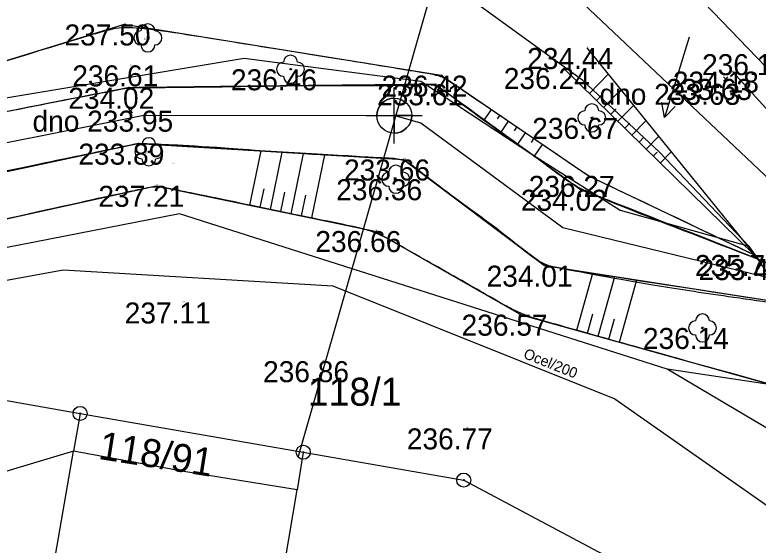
# Model space of a CAD drawing. Extents: x -555757 to -553364, y -1100723 to -1096439.
# Drawn here: x -554111.1 to -554058.1, y -1100615 to -1100577.1 of the extents above; entities that cross this region are included whole.
import ezdxf

# ---------------------------------------------------------------- set-up
doc = ezdxf.new("R2010")
doc.units = 0
for name, color, linetype in [('00_NÁVRH - 0.18 mm', 7, 'Continuous'), ('00_NÁVRH - 0.35 mm', 7, 'Continuous'), ('00_NÁVRH - Kóty výškové', 7, 'Continuous'), ('00_NÁVRH - Řezy', 7, 'Continuous'), ('01_HLADINA', 7, 'Continuous'), ('05_SÍTĚ - plynovod STL', 7, 'Continuous'), ('30', 7, 'Continuous'), ('C$SLO$PARCELY', 7, 'Continuous'), ('Geodet. výšky - netisknuté', 7, 'Continuous'), ('HRANA$SVAHU', 7, 'Continuous'), ('HRANICE$PARCELY', 7, 'Continuous'), ('OSA$KOLEJI', 7, 'Continuous'), ('POPIS', 7, 'Continuous'), ('ROZHRANI', 7, 'Continuous'), ('SLOUPY', 7, 'Continuous'), ('STROMY', 7, 'Continuous'), ('VSTUP', 7, 'Continuous'), ('VYSKA_PODR_BOD', 7, 'Continuous'), ('VYSKOVE$SRAFY', 7, 'Continuous'), ('ZNA$KY$KULTUR', 7, 'Continuous')]:
    doc.layers.add(name, color=color, linetype=linetype)

# ---------------------------------------------------------------- blocks, each defined once
blk = doc.blocks.new('POINT_DISPLAY')
blk.add_line((0, 0), (0, 0))
blk = doc.blocks.new('8$02')
at = {"layer": 'ZNA$KY$KULTUR'}
for p, q in [((0.864, 2.855), (-0.89, -2.882)), ((-0.89, -2.882), (-1.083, -1.802)), ((-0.89, -2.882), (-0.125, -2.095))]:
    blk.add_line(p, q, dxfattribs=at)
blk = doc.blocks.new('1$05')
at = {"layer": 'SLOUPY'}
for radius in [0.5, 0.032]:
    blk.add_circle((0, 0), radius, dxfattribs=at)
blk = doc.blocks.new('BOD')
at = {"layer": 'POPIS'}
for p, q in [((-0.283, -0.283), (0.283, 0.283)), ((-0.283, 0.283), (0.283, -0.283))]:
    blk.add_line(p, q, dxfattribs=at)
blk = doc.blocks.new('3$13')
at = {"layer": 'STROMY'}
blk.add_circle((0, 0), 0.05, dxfattribs=at)
for centre, start, end in [((0, 0.5), 0, 180), ((-0.5, 0), 90, 270), ((0.5, 0), 270, 90), ((0, -0.5), 180, 0)]:
    blk.add_arc(centre, 0.5, start, end, dxfattribs=at)
blk = doc.blocks.new('ZN_Výšková kóta - Půdorys')
for p, q in [((0, -2), (0, 2)), ((-2, 0), (2, 0))]:
    blk.add_line(p, q)
for points in [[(-1.25, 0), (0, 0), (0, 1.25)], [(1.25, 0), (0, 0), (0, -1.25)]]:
    blk.add_lwpolyline(points)
blk.add_circle((0, 0), 1.25)
for start, end in [(90, 180), (270, 0)]:
    blk.add_arc((0, 0), 1.25, start, end)

msp = doc.modelspace()

# ---------------------------------------------------------------- linework, layer by layer
at = {"layer": '00_NÁVRH - 0.18 mm'}
msp.add_lwpolyline([(-554047.016, -1100597.399), (-554056.765, -1100596.021), (-554072.01, -1100592.304), (-554082.146, -1100584.823), (-554084.051, -1100584.283), (-554102.031, -1100584.313), (-554134.225, -1100590.74), (-554163.98, -1100595.962)], dxfattribs=at)
for points in [[(-554058.34, -1100594.24), (-554064.27, -1100591.415), (-554069.894, -1100588.736), (-554070.2, -1100588.59), (-554070.622, -1100588.302), (-554073.49, -1100586.347), (-554075.45, -1100585.01), (-554079.1, -1100582.531), (-554080.049, -1100581.874), (-554080.7, -1100581.481), (-554081.481, -1100581.304), (-554087.875, -1100580.272), (-554092.015, -1100579.605), (-554097.661, -1100578.708), (-554101.142, -1100578.133), (-554103.33, -1100577.967), (-554104.353, -1100578.095), (-554110.104, -1100579.897), (-554119.235, -1100582.7), (-554134.394, -1100587.389), (-554135.14, -1100587.62), (-554135.88, -1100587.767), (-554163.968, -1100593.356), (-554164.64, -1100593.5), (-554165.523, -1100593.676), (-554179.48, -1100596.685), (-554194.32, -1100599.87), (-554206.989, -1100602.104), (-554211.391, -1100602.887), (-554215.452, -1100603.598), (-554218.301, -1100604.127), (-554220.59, -1100604.491), (-554221.645, -1100604.411), (-554222.588, -1100604.119), (-554224.36, -1100602.886), (-554226.55, -1100601.265), (-554230.862, -1100598.151), (-554231.32, -1100597.82), (-554232.374, -1100596.759), (-554235.586, -1100593.426), (-554239.515, -1100589.37), (-554243.986, -1100584.748), (-554247.71, -1100580.92), (-554249.936, -1100577.477), (-554252.665, -1100573.15), (-554257.62, -1100565.38), (-554264.631, -1100555.299), (-554268.645, -1100549.529), (-554269.73, -1100547.97), (-554270.489, -1100547.211), (-554275.85, -1100541.875), (-554281.97, -1100535.78), (-554287.906, -1100531.237), (-554302.937, -1100521.677), (-554058.34, -1100594.24), (-554302.937, -1100521.677)], [(-554047.86, -1100606.09), (-554063.146, -1100601.815), (-554071.814, -1100599.393), (-554074.245, -1100598.71), (-554074.95, -1100598.43), (-554075.799, -1100598.044), (-554076.704, -1100597.516), (-554082.278, -1100594.33), (-554084.54, -1100593.047), (-554085.407, -1100592.634), (-554086.399, -1100592.326), (-554087.509, -1100592.104), (-554096.333, -1100590.269), (-554099.874, -1100589.549), (-554100.557, -1100589.404), (-554101.037, -1100589.369), (-554101.552, -1100589.414), (-554102.59, -1100589.645), (-554107.727, -1100590.768), (-554129.464, -1100595.608), (-554132.384, -1100596.23), (-554132.88, -1100596.318), (-554134.554, -1100596.539), (-554152.022, -1100598.865), (-554161.802, -1100600.155), (-554162.744, -1100600.318), (-554163.338, -1100600.456), (-554165.331, -1100601.02), (-554176.765, -1100604.247), (-554189.626, -1100607.8), (-554194.598, -1100609.179), (-554196.355, -1100609.599), (-554198.704, -1100609.736), (-554203.748, -1100609.834), (-554214.875, -1100610.027), (-554219.792, -1100610.102), (-554223.403, -1100610.173), (-554224.348, -1100610.104), (-554224.869, -1100609.756), (-554225.457, -1100609.217), (-554228.695, -1100606.291), (-554234.196, -1100601.385), (-554241.685, -1100594.776), (-554249.868, -1100587.59), (-554251.102, -1100586.477), (-554253.665, -1100583.954), (-554260.074, -1100577.697), (-554266.777, -1100571.14), (-554267.547, -1100570.379), (-554267.995, -1100569.734), (-554268.443, -1100568.902), (-554268.664, -1100568.278), (-554270.099, -1100564.014), (-554272.97, -1100555.371), (-554273.54, -1100553.674), (-554273.85, -1100553.041), (-554274.307, -1100552.435), (-554274.896, -1100551.869), (-554275.985, -1100550.799), (-554278.698, -1100548.209), (-554284.66, -1100542.226), (-554286.16, -1100540.826), (-554286.536, -1100540.462), (-554286.752, -1100540.28), (-554286.997, -1100540.101), (-554289.311, -1100538.365), (-554299.045, -1100530.122), (-554303.449, -1100525.797), (-554305.461, -1100524.163), (-554047.86, -1100606.09), (-554305.461, -1100524.163)]]:
    msp.add_open_spline(points, degree=3, dxfattribs=at)
at = {"layer": '00_NÁVRH - 0.35 mm'}
for points in [[(-554058.08, -1100594.53), (-554070.098, -1100589.826), (-554070.68, -1100589.568), (-554071.244, -1100589.226), (-554073.155, -1100587.845), (-554079.313, -1100583.371), (-554080.665, -1100582.389), (-554081.17, -1100582.119), (-554081.52, -1100582.062), (-554082.269, -1100582.067), (-554089.112, -1100582.135), (-554095.236, -1100582.205), (-554101.649, -1100582.283), (-554102.788, -1100582.296), (-554103.06, -1100582.309), (-554103.23, -1100582.334), (-554103.751, -1100582.438), (-554104.593, -1100582.601), (-554113.817, -1100584.411), (-554126.39, -1100586.927), (-554134.868, -1100588.581), (-554139.351, -1100589.413), (-554152.634, -1100591.849), (-554164.121, -1100593.961), (-554164.489, -1100594.027), (-554164.726, -1100594.093), (-554171.318, -1100595.904), (-554180.99, -1100598.534), (-554187.345, -1100600.301), (-554193.97, -1100602.124), (-554194.727, -1100602.295), (-554195.31, -1100602.382), (-554198.068, -1100602.675), (-554205.034, -1100603.408), (-554213.288, -1100604.27), (-554219.718, -1100604.954), (-554221.41, -1100605.132), (-554221.976, -1100605.1), (-554222.44, -1100604.894), (-554223.161, -1100604.388), (-554227.803, -1100601.17), (-554231.327, -1100598.718), (-554232.217, -1100598.086), (-554232.626, -1100597.768), (-554232.908, -1100597.519), (-554233.334, -1100597.069), (-554235.292, -1100595.021), (-554239.019, -1100591.072), (-554241.195, -1100588.758), (-554242.89, -1100587.005), (-554246.303, -1100583.394), (-554247.607, -1100582.002), (-554248.038, -1100581.554), (-554248.309, -1100581.263), (-554250.624, -1100578.562), (-554252.687, -1100576.168), (-554254.664, -1100573.87), (-554258.287, -1100569.626), (-554259.888, -1100567.76), (-554260.342, -1100567.276), (-554064.104, -1100592.217), (-554260.117, -1100567.52)], [(-554048.34, -1100598.86), (-554070.494, -1100595.513), (-554072.801, -1100595.085), (-554073.384, -1100594.919), (-554073.629, -1100594.77), (-554076.188, -1100592.81), (-554080.338, -1100589.717), (-554082.053, -1100588.4), (-554083.139, -1100587.602), (-554083.425, -1100587.457), (-554083.874, -1100587.374), (-554085.606, -1100587.272), (-554092.533, -1100586.875), (-554098.787, -1100586.448), (-554101.549, -1100586.32), (-554101.959, -1100586.304), (-554102.334, -1100586.299), (-554102.509, -1100586.325), (-554102.88, -1100586.406), (-554105.009, -1100586.855), (-554113.175, -1100588.561), (-554127.132, -1100591.545), (-554132.193, -1100592.603), (-554133.199, -1100592.792), (-554136.652, -1100593.397), (-554142.159, -1100594.352), (-554151.301, -1100595.864), (-554161.359, -1100597.509), (-554162.891, -1100597.788), (-554163.41, -1100597.88), (-554164.196, -1100598.108), (-554169.985, -1100599.766), (-554183.434, -1100603.703), (-554192.425, -1100606.265), (-554194.622, -1100606.916), (-554195.802, -1100607.195), (-554196.585, -1100607.297), (-554202.368, -1100607.613), (-554208.625, -1100607.981), (-554218.85, -1100608.551), (-554222.453, -1100608.773), (-554223.69, -1100608.711), (-554224.519, -1100608.205), (-554227.182, -1100606.005), (-554229.24, -1100604.267), (-554232.606, -1100601.394), (-554236.172, -1100597.967), (-554240.308, -1100594.05), (-554243.636, -1100590.917), (-554247.063, -1100587.629), (-554249.2, -1100585.633), (-554250.21, -1100584.578), (-554252.743, -1100581.714), (-554256.486, -1100577.473), (-554259.476, -1100574.064), (-554263.368, -1100569.689), (-554263.999, -1100568.988), (-554059.44, -1100597.347), (-554263.697, -1100569.351)]]:
    msp.add_open_spline(points, degree=3, dxfattribs=at)
at = {"layer": '00_NÁVRH - Řezy'}
msp.add_line((-554090.882, -1100608.599), (-554081.334, -1100575.196), dxfattribs=at)
at = {"layer": '01_HLADINA'}
msp.add_line((-554058.08, -1100594.53), (-554048.34, -1100598.86), dxfattribs=at)
msp.add_lwpolyline([(-553953.109, -1100099.324), (-553965.257, -1100164.739), (-553969.414, -1100189.901), (-553974.296, -1100224.075), (-553978.757, -1100270.492), (-553983.948, -1100311.583), (-553989.498, -1100329.147), (-553995.787, -1100344.499), (-554001.618, -1100365.994), (-554010.247, -1100383.721), (-554044.693, -1100426.792), (-554056.928, -1100450.051), (-554073.884, -1100483.251), (-554097.666, -1100514.341), (-554108.96, -1100533.606), (-554110.136, -1100539.01), (-554109.195, -1100543.239), (-554088.698, -1100559.123), (-554040.767, -1100604.471), (-554031.292, -1100609.851)], dxfattribs=at)
for points in [[(-554260.342, -1100567.276), (-554260.192, -1100567.439), (-554259.469, -1100568.191), (-554257.635, -1100570.436), (-554255.214, -1100573.223), (-554252.663, -1100576.204), (-554250.524, -1100578.65), (-554249.026, -1100580.491), (-554247.989, -1100581.61), (-554247.306, -1100582.308), (-554245.613, -1100584.146), (-554243.483, -1100586.405), (-554241.017, -1100588.928), (-554238.507, -1100591.622), (-554235.908, -1100594.413), (-554233.825, -1100596.517), (-554232.973, -1100597.47), (-554232.592, -1100597.802), (-554232.067, -1100598.204), (-554230.449, -1100599.325), (-554227.451, -1100601.451), (-554224.415, -1100603.42), (-554222.561, -1100604.845), (-554221.967, -1100605.148), (-554221.022, -1100605.13), (-554218.156, -1100604.73), (-554212.672, -1100604.228), (-554205.464, -1100603.458), (-554199.472, -1100602.801), (-554196.032, -1100602.481), (-554194.664, -1100602.296), (-554191.996, -1100601.637), (-554187.438, -1100600.312), (-554179.889, -1100598.229), (-554172.348, -1100596.161), (-554166.833, -1100594.723), (-554164.449, -1100594.01), (-554160.387, -1100593.403), (-554152.051, -1100591.669), (-554142.282, -1100589.959), (-554133.53, -1100588.339), (-554125.021, -1100586.662), (-554114.936, -1100584.634), (-554107.392, -1100583.124), (-554103.857, -1100582.463), (-554103.349, -1100582.353), (-554103.027, -1100582.3), (-554102.499, -1100582.291), (-554099.893, -1100582.268), (-554095.332, -1100582.211), (-554088.874, -1100582.101), (-554084.296, -1100582.166), (-554081.653, -1100582.039), (-554081.09, -1100582.109), (-554080.348, -1100582.59), (-554077.753, -1100584.564), (-554074.541, -1100586.778), (-554071.725, -1100588.923), (-554070.696, -1100589.582), (-554066.303, -1100591.373), (-554062.092, -1100592.99), (-554058.08, -1100594.53)], [(-554048.34, -1100598.86), (-554055.765, -1100597.848), (-554063.967, -1100596.73), (-554072.22, -1100595.196), (-554073.3, -1100594.989), (-554074.451, -1100594.226), (-554076.662, -1100592.363), (-554079.544, -1100590.333), (-554081.847, -1100588.576), (-554082.835, -1100587.769), (-554083.459, -1100587.417), (-554084.305, -1100587.325), (-554087.328, -1100587.208), (-554092.317, -1100586.912), (-554097.618, -1100586.493), (-554100.766, -1100586.347), (-554101.947, -1100586.307), (-554102.269, -1100586.284), (-554102.576, -1100586.336), (-554103.463, -1100586.544), (-554107.026, -1100587.257), (-554115.108, -1100588.971), (-554124.168, -1100590.895), (-554130.834, -1100592.35), (-554134.012, -1100592.945), (-554137.337, -1100593.511), (-554143.365, -1100594.57), (-554151.599, -1100595.946), (-554158.536, -1100596.953), (-554162.55, -1100597.739), (-554163.509, -1100597.883), (-554165.846, -1100598.659), (-554172.57, -1100600.405), (-554181.916, -1100603.355), (-554190.181, -1100605.564), (-554194.271, -1100606.83), (-554195.659, -1100607.194), (-554198.243, -1100607.489), (-554202.532, -1100607.568), (-554209.934, -1100608.089), (-554216.694, -1100608.43), (-554221.62, -1100608.702), (-554223.647, -1100608.868), (-554225.209, -1100607.689), (-554226.98, -1100606.174), (-554229.679, -1100603.887), (-554232.787, -1100601.338), (-554236.329, -1100597.767), (-554240.032, -1100594.305), (-554243.696, -1100590.893), (-554246.592, -1100588.017), (-554248.874, -1100585.998), (-554250.757, -1100584.011), (-554253.133, -1100581.244), (-554256.243, -1100577.758), (-554259.77, -1100573.735), (-554262.24, -1100570.883), (-554263.798, -1100569.23), (-554263.999, -1100568.988)]]:
    msp.add_open_spline(points, degree=3, dxfattribs=at)
at = {"layer": '05_SÍTĚ - plynovod STL'}
msp.add_lwpolyline([(-554137.436, -1100602.126), (-554131.255, -1100599.61), (-554107.686, -1100595.295), (-554088.428, -1100596.446), (-554068.308, -1100604.5), (-554031.805, -1100630.099), (-554025.489, -1100640.66)], dxfattribs=at)
at = {"layer": 'HRANA$SVAHU'}
for p, q in [((-554103.33, -1100577.78), (-554135.14, -1100587.62)), ((-554080.7, -1100581.43), (-554103.33, -1100577.78)), ((-554070.31, -1100579.46), (-554058.08, -1100594.53)), ((-554071.98, -1100580.89), (-554058.34, -1100594.24)), ((-554053.04, -1100588.72), (-554059.91, -1100581.15)), ((-554070.2, -1100588.59), (-554080.7, -1100581.43)), ((-554103.06, -1100582.3), (-554134.85, -1100588.58)), ((-554081.15, -1100582.05), (-554103.06, -1100582.3)), ((-554070.76, -1100589.58), (-554081.15, -1100582.05)), ((-554133.6, -1100592.9), (-554102.34, -1100586.29)), ((-554102.34, -1100586.29), (-554083.38, -1100587.42)), ((-554083.38, -1100587.42), (-554073.33, -1100595)), ((-554058.34, -1100594.24), (-554070.2, -1100588.59)), ((-554132.61, -1100596.28), (-554101.04, -1100589.3)), ((-554101.04, -1100589.3), (-554085.43, -1100592.53)), ((-554058.08, -1100594.53), (-554070.76, -1100589.58)), ((-554085.43, -1100592.53), (-554074.99, -1100598.5)), ((-554073.33, -1100595), (-554048.34, -1100598.86)), ((-554074.99, -1100598.5), (-554047.86, -1100606.09))]:
    msp.add_line(p, q, dxfattribs=at)
at = {"layer": 'HRANICE$PARCELY'}
for p, q in [((-554058.73, -1100593.62), (-554051.47, -1100604.36)), ((-554051.47, -1100604.36), (-554064.58, -1100602.38)), ((-554106.47, -1100605.55), (-554106.94, -1100608.24)), ((-554106.47, -1100605.55), (-554090.54, -1100608.32)), ((-554113.5, -1100645.85), (-554106.94, -1100608.24)), ((-554090.54, -1100608.32), (-554090.98, -1100611.01)), ((-554097.23, -1100647.61), (-554090.98, -1100611.01))]:
    msp.add_line(p, q, dxfattribs=at)
for points in [[(-553962.24, -1100635.46), (-553968.69, -1100627.95), (-553995.16, -1100618.35), (-554029.74, -1100603.52), (-554045.68, -1100593.11), (-554081.91, -1100555.45)], [(-554258.8, -1100566.36), (-554251.34, -1100579.17), (-554238.95, -1100591.02), (-554228.15, -1100603.38), (-554221.97, -1100606.75), (-554124.66, -1100585.15), (-554094.77, -1100580.19)], [(-554058.73, -1100593.62), (-554065.12, -1100586.9), (-554070.58, -1100581.77), (-554078.35, -1100576.17)], [(-554094.77, -1100580.19), (-554082.16, -1100581.82), (-554074.16, -1100587.09), (-554067.92, -1100591.05), (-554058.73, -1100593.62)], [(-554064.58, -1100602.38), (-554099.37, -1100591.3), (-554168.19, -1100604.75), (-554175.95, -1100606.8)], [(-554030.45, -1100625.78), (-554040.31, -1100616.76), (-554064.58, -1100602.38)], [(-554123.1, -1100606.79), (-554112.67, -1100604.47), (-554106.47, -1100605.55)], [(-554106.94, -1100608.24), (-554115.61, -1100610.85), (-554124.27, -1100613.37)], [(-554090.98, -1100611.01), (-554099.06, -1100609.69), (-554106.94, -1100608.24)], [(-554090.54, -1100608.32), (-554079.09, -1100610.31), (-554066.52, -1100617.01)]]:
    msp.add_lwpolyline(points, dxfattribs=at)
at = {"layer": 'VYSKOVE$SRAFY'}
for p, q in [((-554070.123, -1100582.708), (-554068.784, -1100581.34)), ((-554069.616, -1100583.204), (-554069.189, -1100582.768)), ((-554069.109, -1100583.7), (-554067.884, -1100582.449)), ((-554077.139, -1100583.858), (-554077.64, -1100584.594)), ((-554068.602, -1100584.196), (-554068.213, -1100583.799)), ((-554068.095, -1100584.692), (-554066.984, -1100583.558)), ((-554076.531, -1100584.273), (-554076.702, -1100584.524)), ((-554075.922, -1100584.688), (-554076.448, -1100585.458)), ((-554067.588, -1100585.188), (-554067.237, -1100584.83)), ((-554067.081, -1100585.685), (-554066.085, -1100584.666)), ((-554075.314, -1100585.103), (-554075.493, -1100585.365)), ((-554074.706, -1100585.517), (-554075.255, -1100586.323)), ((-554074.098, -1100585.932), (-554074.285, -1100586.206)), ((-554066.574, -1100586.181), (-554066.261, -1100585.86)), ((-554066.067, -1100586.677), (-554065.185, -1100585.775)), ((-554073.49, -1100586.347), (-554074.062, -1100587.187)), ((-554094.352, -1100590.684), (-554093.552, -1100586.814)), ((-554092.88, -1100590.988), (-554092.035, -1100586.904)), ((-554091.409, -1100591.293), (-554090.519, -1100586.995)), ((-554089.937, -1100591.597), (-554089.003, -1100587.085)), ((-554065.561, -1100587.173), (-554065.285, -1100586.892)), ((-554065.054, -1100587.669), (-554064.285, -1100586.884)), ((-554093.616, -1100590.836), (-554093.342, -1100589.51)), ((-554092.145, -1100591.141), (-554091.854, -1100589.744)), ((-554090.673, -1100591.445), (-554090.369, -1100589.977)), ((-554071.01, -1100599.614), (-554069.869, -1100595.535)), ((-554069.495, -1100600.037), (-554068.303, -1100595.777)), ((-554067.979, -1100600.461), (-554066.737, -1100596.018)), ((-554070.252, -1100599.825), (-554069.864, -1100598.435)), ((-554068.737, -1100600.249), (-554068.331, -1100598.799))]:
    msp.add_line(p, q, dxfattribs=at)

# ---------------------------------------------------------------- block references
at = {"layer": '00_NÁVRH - Kóty výškové'}
msp.add_blockref('ZN_Výšková kóta - Půdorys', (-554084.051, -1100584.283), dxfattribs=at)
at = {"layer": 'POPIS', "xscale": 0.5624965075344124, "yscale": 0.5624965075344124}
for p in [(-554060.4, -1100581.67), (-554102.89, -1100583.93)]:
    msp.add_blockref('BOD', p, dxfattribs=at)
at = {"layer": 'ROZHRANI'}
for p in [(-554103.33, -1100577.78), (-554101.63, -1100578.74), (-554070.31, -1100579.46), (-554102.9, -1100580.7), (-554091.45, -1100580.98), (-554071.98, -1100580.89), (-554059.91, -1100581.15), (-554080.7, -1100581.43), (-554060.4, -1100581.67), (-554103.06, -1100582.3), (-554081.15, -1100582.05), (-554102.89, -1100583.93), (-554069.95, -1100584.45), (-554102.34, -1100586.29), (-554101.56, -1100586.87), (-554083.38, -1100587.42), (-554070.2, -1100588.59), (-554083.94, -1100588.83), (-554101.04, -1100589.3), (-554070.76, -1100589.58), (-554085.43, -1100592.53), (-554058.34, -1100594.24), (-554058.08, -1100594.53), (-554073.33, -1100595), (-554099.16, -1100597.63), (-554074.99, -1100598.5), (-554062.05, -1100599.45), (-554089.16, -1100601.82), (-554078.9, -1100606.62)]:
    msp.add_blockref('POINT_DISPLAY', p, dxfattribs=at)
at = {"layer": 'STROMY'}
for p in [(-554101.63, -1100578.74), (-554091.45, -1100580.98), (-554069.95, -1100584.45), (-554101.56, -1100586.87), (-554083.94, -1100588.83), (-554062.05, -1100599.45)]:
    msp.add_blockref('3$13', p, dxfattribs=at)
at = {"layer": 'VSTUP'}
for p in [(-554106.47, -1100605.55), (-554090.54, -1100608.32), (-554079.09, -1100610.31)]:
    msp.add_blockref('1$05', p, dxfattribs=at)
at = {"layer": 'ZNA$KY$KULTUR'}
msp.add_blockref('8$02', (-554063.87, -1100581.54), dxfattribs=at)

# ---------------------------------------------------------------- texts
at = {"layer": '30'}
msp.add_text('Ocel/200', height=0.75, rotation=338.1839, dxfattribs=at).set_placement((-554074.885, -1100601.574))
at = {"layer": 'C$SLO$PARCELY'}
msp.add_text('118/1', height=2, dxfattribs=at).set_placement((-554090.221, -1100605))
msp.add_text('118/91', height=2, rotation=351, dxfattribs=at).set_placement((-554105.223, -1100608.791))
at = {"layer": 'Geodet. výšky - netisknuté'}
for s, p in [('237.31', (-554101.905, -1100578.84)), ('233.95', (-554103.173, -1100584.03)), ('236.41', (-554101.835, -1100586.97)), ('3x', (-554099.873, -1100587.744))]:
    msp.add_text(s, height=0.1, dxfattribs=at).set_placement(p)
at = {"layer": 'OSA$KOLEJI'}
for s, p in [('54', (-554103.33, -1100577.78)), ('53', (-554101.63, -1100578.74)), ('37', (-554070.31, -1100579.46)), ('55', (-554102.9, -1100580.7)), ('52', (-554091.45, -1100580.98)), ('36', (-554071.98, -1100580.89)), ('15', (-554059.91, -1100581.15)), ('46', (-554080.7, -1100581.43)), ('16', (-554060.4, -1100581.67)), ('56', (-554103.06, -1100582.3)), ('47', (-554081.15, -1100582.05)), ('58', (-554102.89, -1100583.93)), ('35', (-554069.95, -1100584.45)), ('57', (-554102.34, -1100586.29)), ('61', (-554101.56, -1100586.87)), ('51', (-554083.38, -1100587.42)), ('41', (-554070.2, -1100588.59)), ('59', (-554101.04, -1100589.3)), ('50', (-554083.94, -1100588.83)), ('44', (-554070.76, -1100589.58)), ('48', (-554085.43, -1100592.53)), ('38', (-554058.34, -1100594.24)), ('45', (-554073.33, -1100595)), ('60', (-554099.16, -1100597.63)), ('42', (-554074.99, -1100598.5)), ('40', (-554062.05, -1100599.45)), ('49', (-554089.16, -1100601.82)), ('43', (-554078.9, -1100606.62))]:
    msp.add_text(s, height=0.1, dxfattribs=at).set_placement(p)
at = {"layer": 'POPIS'}
for s, p in [('dno 233.63', (-554069.4, -1100583.517)), ('dno 233.95', (-554109.863, -1100585.436))]:
    msp.add_text(s, height=1.5, dxfattribs=at).set_placement(p)
at = {"layer": 'VYSKA_PODR_BOD'}
for s, p in [('237.50', (-554107.58, -1100579.28)), ('234.44', (-554074.56, -1100580.96)), ('236.19', (-554062.08, -1100581.4)), ('236.61', (-554107.025, -1100582.2)), ('236.46', (-554095.7, -1100582.48)), ('236.24', (-554076.23, -1100582.39)), ('234.18', (-554064.16, -1100582.65)), ('236.42', (-554084.95, -1100582.93)), ('233.63', (-554064.65, -1100583.17)), ('234.02', (-554107.31, -1100583.8)), ('233.61', (-554085.275, -1100583.55)), ('236.67', (-554074.2, -1100585.95)), ('233.89', (-554106.59, -1100587.79)), ('233.66', (-554087.63, -1100588.92)), ('236.27', (-554074.45, -1100590.09)), ('236.36', (-554088.19, -1100590.33)), ('237.21', (-554105.165, -1100590.8)), ('234.02', (-554075.01, -1100591.08)), ('236.66', (-554089.68, -1100594.03)), ('235.72', (-554062.59, -1100595.74)), ('233.43', (-554062.33, -1100596.03)), ('234.01', (-554077.455, -1100596.5)), ('237.11', (-554103.285, -1100599.13)), ('236.57', (-554079.24, -1100600)), ('236.14', (-554066.3, -1100600.95)), ('236.86', (-554093.41, -1100603.32)), ('236.77', (-554083.15, -1100608.12))]:
    msp.add_text(s, height=1.5, dxfattribs=at).set_placement(p)

doc.saveas('drawing.dxf')
